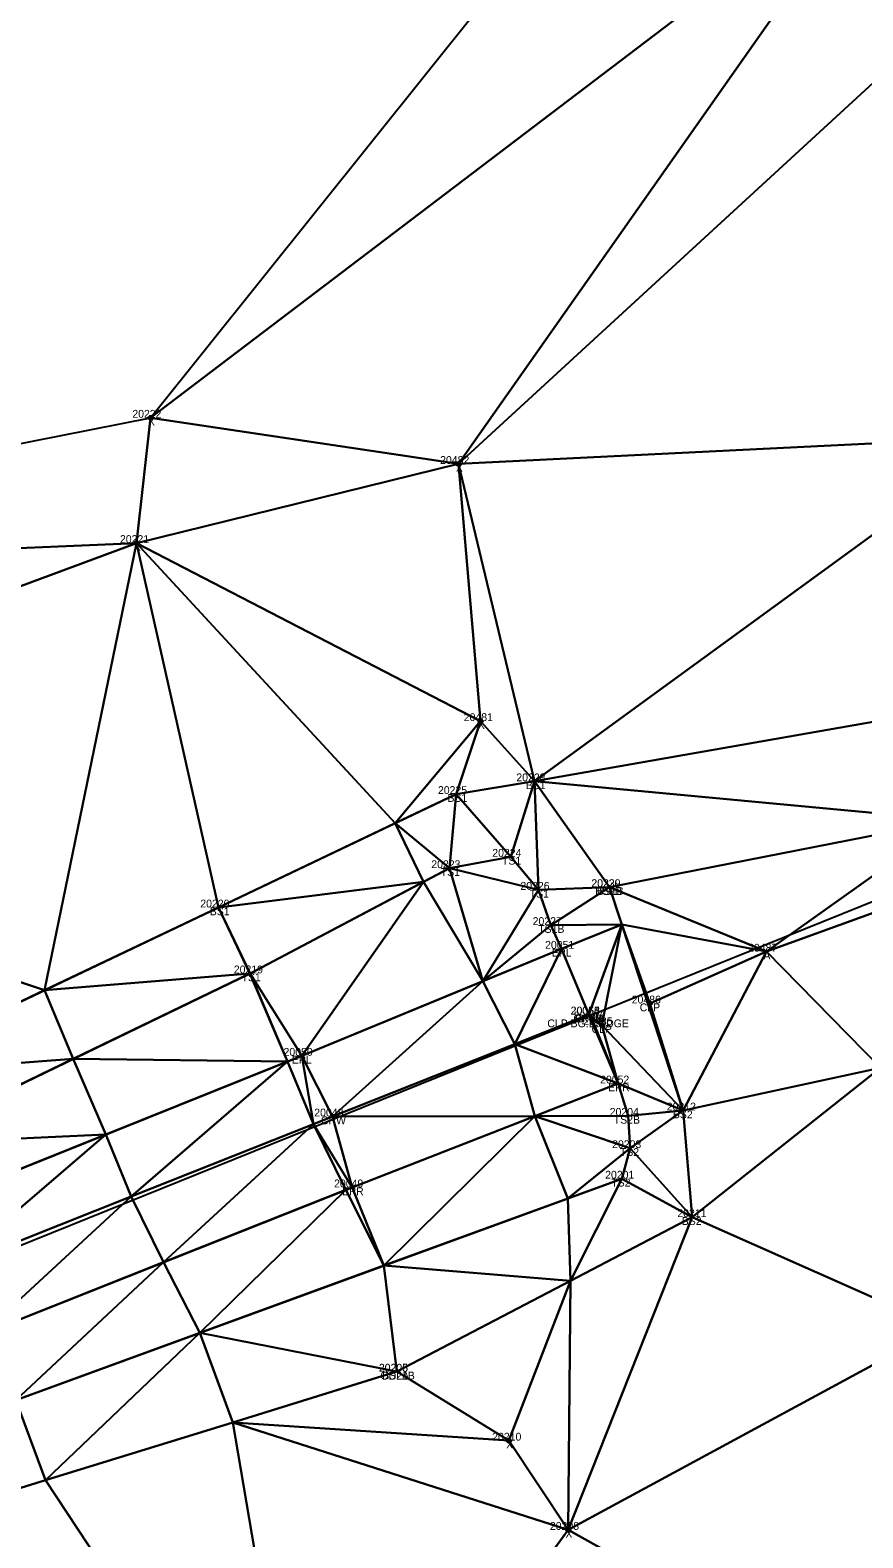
# Model space of a CAD drawing. Extents: x 1966740 to 1969291, y 1117379 to 1118460.
# Drawn here: x 1967626.6 to 1967732.8, y 1117756 to 1117948.4 of the extents above; entities that cross this region are included whole.
import ezdxf

# ---------------------------------------------------------------- set-up
doc = ezdxf.new("R2010")
doc.units = 0
for name, color, linetype in [('Level 1', 7, 'Continuous'), ('Level 3', 7, 'Continuous'), ('Level 30', 7, 'Continuous'), ('Level 35', 7, 'Continuous'), ('Level 50', 7, 'Continuous'), ('Level 52', 7, 'Continuous'), ('Level 53', 7, 'Continuous'), ('Level 56', 7, 'Continuous'), ('Level 6', 7, 'Continuous'), ('Level 62', 7, 'Continuous')]:
    doc.layers.add(name, color=color, linetype=linetype)

msp = doc.modelspace()

# ---------------------------------------------------------------- linework, layer by layer
at = {"layer": 'Level 1'}
msp.add_line((1966770.74, 1117448.12), (1967849.47, 1117883.86), dxfattribs=at)
at = {"layer": 'Level 3'}
for points in [[(1967560.73, 1117793.63), (1967650.63, 1117836.46), (1967680.95, 1117850.94), (1967690.95, 1117852.56), (1967700.5, 1117839.06)], [(1966768.15, 1117461.43), (1966869.41, 1117499.34), (1967070.52, 1117582.35), (1967171.25, 1117624.02), (1967269.74, 1117664.9), (1967320.21, 1117685.71), (1967369.37, 1117708.48), (1967468.51, 1117746.66), (1967564.6, 1117784.47), (1967654.68, 1117828.05), (1967680.1, 1117841.48), (1967687.91, 1117842.93), (1967691.45, 1117838.71), (1967693.03, 1117834.22)], [(1967673.4, 1117777.22), (1967711.06, 1117796.94), (1967709.93, 1117810.55), (1967700.5, 1117839.06)], [(1966769.51, 1117457.48), (1966870.16, 1117497.34), (1966971.19, 1117538.95), (1967071.09, 1117580.24), (1967172.6, 1117621.53), (1967270.79, 1117661.66), (1967321.12, 1117682.57), (1967371.52, 1117702.88), (1967470.26, 1117741.55), (1967566.67, 1117779.5), (1967661.25, 1117817.53), (1967694.4, 1117831.19), (1967697.89, 1117822.8)], [(1966772.57, 1117449.88), (1966874.49, 1117489.87), (1966974.64, 1117529.93), (1967075.06, 1117571.68), (1967175.91, 1117613.34), (1967274.11, 1117653.69), (1967325.25, 1117674.8), (1967374.73, 1117695.01), (1967473.9, 1117733.1), (1967569.8, 1117771.9), (1967665.19, 1117809.79), (1967697.89, 1117822.8)], [(1967340.03, 1117669.86), (1967379.26, 1117686.2), (1967476.09, 1117724.39), (1967573.92, 1117763.51), (1967667.7, 1117800.74), (1967701.64, 1117814), (1967697.89, 1117822.8)], [(1967334.06, 1117655.75), (1967334.81, 1117659.44), (1967379.1, 1117675.46), (1967480.83, 1117718.27), (1967577.81, 1117756.42), (1967702.07, 1117801.85), (1967703.17, 1117805.75), (1967702.89, 1117809.87)]]:
    msp.add_lwpolyline(points, dxfattribs=at)
at = {"layer": 'Level 30'}
for centre in [(1967641.96, 1117898.96), (1967681.25, 1117893.06), (1967640.16, 1117882.97), (1967684.04, 1117860.25), (1967705.67, 1117824.21), (1967698.29, 1117822.17), (1967699.54, 1117821.44), (1967687.66, 1117768.42), (1967695.23, 1117757.03)]:
    msp.add_circle(centre, 0.25, dxfattribs=at)
at = {"layer": 'Level 35'}
for points in [[(1967641.96, 1117898.96), (1967761.22, 1118047.98), (1967735.17, 1117969.82)], [(1967641.96, 1117898.96), (1967735.17, 1117969.82), (1967681.25, 1117893.06)], [(1967681.25, 1117893.06), (1967735.17, 1117969.82), (1967736.25, 1117943.61)], [(1967681.25, 1117893.06), (1967736.25, 1117943.61), (1967751.24, 1117896.51)], [(1967539.35, 1117878.65), (1967641.96, 1117898.96), (1967640.16, 1117882.97)], [(1967640.16, 1117882.97), (1967641.96, 1117898.96), (1967681.25, 1117893.06)], [(1967681.25, 1117893.06), (1967751.24, 1117896.51), (1967690.95, 1117852.56)], [(1967690.95, 1117852.56), (1967751.24, 1117896.51), (1967752.37, 1117863.36)], [(1967640.16, 1117882.97), (1967681.25, 1117893.06), (1967684.04, 1117860.25)], [(1967681.25, 1117893.06), (1967690.95, 1117852.56), (1967684.04, 1117860.25)], [(1967539.35, 1117878.65), (1967640.16, 1117882.97), (1967553.36, 1117850.76)], [(1967553.36, 1117850.76), (1967640.16, 1117882.97), (1967628.44, 1117825.89)], [(1967628.44, 1117825.89), (1967640.16, 1117882.97), (1967650.63, 1117836.46)], [(1967640.16, 1117882.97), (1967684.04, 1117860.25), (1967673.18, 1117847.23)], [(1967640.16, 1117882.97), (1967673.18, 1117847.23), (1967650.63, 1117836.46)], [(1967690.95, 1117852.56), (1967752.37, 1117863.36), (1967744.11, 1117847.6)], [(1967673.18, 1117847.23), (1967684.04, 1117860.25), (1967680.95, 1117850.94)], [(1967680.95, 1117850.94), (1967684.04, 1117860.25), (1967690.95, 1117852.56)], [(1967680.95, 1117850.94), (1967690.95, 1117852.56), (1967687.91, 1117842.93)], [(1967687.91, 1117842.93), (1967690.95, 1117852.56), (1967691.45, 1117838.71)], [(1967690.95, 1117852.56), (1967744.11, 1117847.6), (1967700.5, 1117839.06)], [(1967690.95, 1117852.56), (1967700.5, 1117839.06), (1967691.45, 1117838.71)], [(1967553.36, 1117850.76), (1967628.44, 1117825.89), (1967605.87, 1117815.14)], [(1967673.18, 1117847.23), (1967680.95, 1117850.94), (1967680.1, 1117841.48)], [(1967680.1, 1117841.48), (1967680.95, 1117850.94), (1967687.91, 1117842.93)], [(1967700.5, 1117839.06), (1967744.11, 1117847.6), (1967720.54, 1117830.82)], [(1967720.54, 1117830.82), (1967744.11, 1117847.6), (1967739.07, 1117837.57)], [(1967650.63, 1117836.46), (1967673.18, 1117847.23), (1967676.78, 1117839.73)], [(1967673.18, 1117847.23), (1967680.1, 1117841.48), (1967676.78, 1117839.73)], [(1967680.1, 1117841.48), (1967687.91, 1117842.93), (1967691.45, 1117838.71)], [(1967676.78, 1117839.73), (1967680.1, 1117841.48), (1967684.36, 1117827.05)], [(1967680.1, 1117841.48), (1967691.45, 1117838.71), (1967684.36, 1117827.05)], [(1967650.63, 1117836.46), (1967676.78, 1117839.73), (1967654.68, 1117828.05)], [(1967654.68, 1117828.05), (1967676.78, 1117839.73), (1967661.25, 1117817.53)], [(1967661.25, 1117817.53), (1967676.78, 1117839.73), (1967684.36, 1117827.05)], [(1967684.36, 1117827.05), (1967691.45, 1117838.71), (1967693.03, 1117834.22)], [(1967691.45, 1117838.71), (1967700.5, 1117839.06), (1967693.03, 1117834.22)], [(1967693.03, 1117834.22), (1967700.5, 1117839.06), (1967702.08, 1117834.28)], [(1967700.5, 1117839.06), (1967720.54, 1117830.82), (1967702.08, 1117834.28)], [(1967628.44, 1117825.89), (1967650.63, 1117836.46), (1967654.61, 1117828.02)], [(1967650.63, 1117836.46), (1967654.68, 1117828.05), (1967654.61, 1117828.02)], [(1967720.54, 1117830.82), (1967739.07, 1117837.57), (1967735.1, 1117816)], [(1967684.36, 1117827.05), (1967693.03, 1117834.22), (1967694.4, 1117831.19)], [(1967693.03, 1117834.22), (1967702.08, 1117834.28), (1967694.4, 1117831.19)], [(1967694.4, 1117831.19), (1967702.08, 1117834.28), (1967697.89, 1117822.8)], [(1967697.89, 1117822.8), (1967702.08, 1117834.28), (1967699.54, 1117821.44)], [(1967699.54, 1117821.44), (1967702.08, 1117834.28), (1967709.93, 1117810.55)], [(1967702.08, 1117834.28), (1967720.54, 1117830.82), (1967705.67, 1117824.21)], [(1967702.08, 1117834.28), (1967705.67, 1117824.21), (1967709.93, 1117810.55)], [(1967684.36, 1117827.05), (1967694.4, 1117831.19), (1967688.42, 1117819.03)], [(1967688.42, 1117819.03), (1967694.4, 1117831.19), (1967697.89, 1117822.8)], [(1967705.67, 1117824.21), (1967720.54, 1117830.82), (1967709.93, 1117810.55)], [(1967709.93, 1117810.55), (1967720.54, 1117830.82), (1967735.1, 1117816)], [(1967628.44, 1117825.89), (1967654.61, 1117828.02), (1967632.11, 1117817.13)], [(1967632.11, 1117817.13), (1967654.61, 1117828.02), (1967659.45, 1117816.8)], [(1967654.61, 1117828.02), (1967654.68, 1117828.05), (1967659.45, 1117816.8)], [(1967654.68, 1117828.05), (1967661.25, 1117817.53), (1967659.45, 1117816.8)], [(1967661.25, 1117817.53), (1967684.36, 1117827.05), (1967665.19, 1117809.79)], [(1967665.19, 1117809.79), (1967684.36, 1117827.05), (1967688.42, 1117819.03)], [(1967605.87, 1117815.14), (1967628.44, 1117825.89), (1967632.11, 1117817.13)], [(1967688.42, 1117819.03), (1967697.89, 1117822.8), (1967701.64, 1117814)], [(1967697.89, 1117822.8), (1967699.54, 1117821.44), (1967698.29, 1117822.17)], [(1967697.89, 1117822.8), (1967698.29, 1117822.17), (1967701.64, 1117814)], [(1967698.29, 1117822.17), (1967699.54, 1117821.44), (1967701.64, 1117814)], [(1967699.54, 1117821.44), (1967709.93, 1117810.55), (1967701.64, 1117814)], [(1967665.19, 1117809.79), (1967688.42, 1117819.03), (1967690.99, 1117809.84)], [(1967688.42, 1117819.03), (1967701.64, 1117814), (1967690.99, 1117809.84)], [(1967605.87, 1117815.14), (1967632.11, 1117817.13), (1967609.61, 1117806.25)], [(1967609.61, 1117806.25), (1967632.11, 1117817.13), (1967636.26, 1117807.48)], [(1967632.11, 1117817.13), (1967659.45, 1117816.8), (1967636.26, 1117807.48)], [(1967636.26, 1117807.48), (1967659.45, 1117816.8), (1967639.5, 1117799.59)], [(1967639.5, 1117799.59), (1967659.45, 1117816.8), (1967662.74, 1117808.82)], [(1967659.45, 1117816.8), (1967661.25, 1117817.53), (1967662.74, 1117808.82)], [(1967661.25, 1117817.53), (1967665.19, 1117809.79), (1967662.74, 1117808.82)], [(1967709.93, 1117810.55), (1967735.1, 1117816), (1967711.06, 1117796.94)], [(1967711.06, 1117796.94), (1967735.1, 1117816), (1967742.85, 1117782.8)], [(1967690.99, 1117809.84), (1967701.64, 1117814), (1967702.89, 1117809.87)], [(1967701.64, 1117814), (1967709.93, 1117810.55), (1967702.89, 1117809.87)], [(1967662.74, 1117808.82), (1967665.19, 1117809.79), (1967667.7, 1117800.74)], [(1967665.19, 1117809.79), (1967690.99, 1117809.84), (1967667.7, 1117800.74)], [(1967667.7, 1117800.74), (1967690.99, 1117809.84), (1967671.73, 1117790.76)], [(1967671.73, 1117790.76), (1967690.99, 1117809.84), (1967695.2, 1117799.34)], [(1967690.99, 1117809.84), (1967702.89, 1117809.87), (1967703.17, 1117805.75)], [(1967690.99, 1117809.84), (1967703.17, 1117805.75), (1967695.2, 1117799.34)], [(1967702.89, 1117809.87), (1967709.93, 1117810.55), (1967703.17, 1117805.75)], [(1967703.17, 1117805.75), (1967709.93, 1117810.55), (1967711.06, 1117796.94)], [(1967609.61, 1117806.25), (1967636.26, 1117807.48), (1967613.06, 1117798.15)], [(1967613.06, 1117798.15), (1967636.26, 1117807.48), (1967616.27, 1117790.36)], [(1967616.27, 1117790.36), (1967636.26, 1117807.48), (1967639.5, 1117799.59)], [(1967639.5, 1117799.59), (1967662.74, 1117808.82), (1967643.63, 1117791.18)], [(1967643.63, 1117791.18), (1967662.74, 1117808.82), (1967666.86, 1117800.41)], [(1967662.74, 1117808.82), (1967667.7, 1117800.74), (1967666.86, 1117800.41)], [(1967695.2, 1117799.34), (1967703.17, 1117805.75), (1967702.07, 1117801.85)], [(1967702.07, 1117801.85), (1967703.17, 1117805.75), (1967711.06, 1117796.94)], [(1967695.2, 1117799.34), (1967702.07, 1117801.85), (1967695.53, 1117788.81)], [(1967695.53, 1117788.81), (1967702.07, 1117801.85), (1967711.06, 1117796.94)], [(1967616.27, 1117790.36), (1967639.5, 1117799.59), (1967620.39, 1117781.96)], [(1967620.39, 1117781.96), (1967639.5, 1117799.59), (1967643.63, 1117791.18)], [(1967643.63, 1117791.18), (1967666.86, 1117800.41), (1967648.25, 1117782.17)], [(1967648.25, 1117782.17), (1967666.86, 1117800.41), (1967671.73, 1117790.76)], [(1967666.86, 1117800.41), (1967667.7, 1117800.74), (1967671.73, 1117790.76)], [(1967671.73, 1117790.76), (1967695.2, 1117799.34), (1967695.53, 1117788.81)], [(1967695.23, 1117757.03), (1967695.53, 1117788.81), (1967711.06, 1117796.94)], [(1967695.23, 1117757.03), (1967711.06, 1117796.94), (1967742.85, 1117782.8)], [(1967620.39, 1117781.96), (1967643.63, 1117791.18), (1967624.77, 1117773.59)], [(1967624.77, 1117773.59), (1967643.63, 1117791.18), (1967648.25, 1117782.17)], [(1967648.25, 1117782.17), (1967671.73, 1117790.76), (1967673.4, 1117777.22)], [(1967671.73, 1117790.76), (1967695.53, 1117788.81), (1967673.4, 1117777.22)], [(1967673.4, 1117777.22), (1967695.53, 1117788.81), (1967687.66, 1117768.42)], [(1967687.66, 1117768.42), (1967695.53, 1117788.81), (1967695.23, 1117757.03)], [(1967624.77, 1117773.59), (1967648.25, 1117782.17), (1967628.56, 1117763.37)], [(1967628.56, 1117763.37), (1967648.25, 1117782.17), (1967652.44, 1117770.75)], [(1967648.25, 1117782.17), (1967673.4, 1117777.22), (1967652.44, 1117770.75)], [(1967695.23, 1117757.03), (1967742.85, 1117782.8), (1967729.44, 1117737.88)], [(1967652.44, 1117770.75), (1967673.4, 1117777.22), (1967687.66, 1117768.42)], [(1967604.68, 1117755.99), (1967624.77, 1117773.59), (1967628.56, 1117763.37)], [(1967628.56, 1117763.37), (1967652.44, 1117770.75), (1967662.45, 1117711.98)], [(1967652.44, 1117770.75), (1967687.66, 1117768.42), (1967695.23, 1117757.03)], [(1967652.44, 1117770.75), (1967695.23, 1117757.03), (1967662.45, 1117711.98)], [(1967604.68, 1117755.99), (1967628.56, 1117763.37), (1967662.45, 1117711.98)], [(1967662.45, 1117711.98), (1967695.23, 1117757.03), (1967729.44, 1117737.88)]]:
    msp.add_lwpolyline(points, close=True, dxfattribs=at)
at = {"layer": 'Level 50'}
for centre in [(1967690.95, 1117852.56), (1967680.95, 1117850.94), (1967687.91, 1117842.93), (1967680.1, 1117841.48), (1967691.45, 1117838.71), (1967700.5, 1117839.06), (1967700.5, 1117839.06), (1967650.63, 1117836.46), (1967693.03, 1117834.22), (1967694.4, 1117831.19), (1967720.54, 1117830.82), (1967654.68, 1117828.05), (1967697.89, 1117822.8), (1967697.89, 1117822.8), (1967697.89, 1117822.8), (1967661.25, 1117817.53), (1967701.64, 1117814), (1967665.19, 1117809.79), (1967702.89, 1117809.87), (1967709.93, 1117810.55), (1967703.17, 1117805.75), (1967702.07, 1117801.85), (1967667.7, 1117800.74), (1967711.06, 1117796.94), (1967673.4, 1117777.22), (1967673.4, 1117777.22)]:
    msp.add_circle(centre, 0.001, dxfattribs=at)
at = {"layer": 'Level 6'}
for points in [[(1967720.54, 1117830.82), (1967739.07, 1117837.57), (1967744.11, 1117847.6), (1967769.01, 1117857.07), (1967779.54, 1117863.12), (1967775.75, 1117875.07), (1967791.02, 1117881), (1967800.46, 1117876.52)], [(1967336.04, 1117656.91), (1967380.56, 1117671.84), (1967483.89, 1117710.7), (1967580.8, 1117748.62), (1967673.4, 1117777.22)]]:
    msp.add_lwpolyline(points, dxfattribs=at)

# ---------------------------------------------------------------- texts
at = {"layer": 'Level 52'}
for s, p in [('20222', (1967639.64, 1117898.96)), ('20482', (1967678.91, 1117893.06)), ('20221', (1967638.06, 1117882.97)), ('20481', (1967681.92, 1117860.25)), ('20486', (1967703.35, 1117824.21)), ('20477', (1967695.94, 1117822.17)), ('20485', (1967697.19, 1117821.44)), ('20210', (1967685.55, 1117768.42)), ('20208', (1967692.91, 1117757.03))]:
    msp.add_text(s, height=1, dxfattribs=at).set_placement(p)
at = {"layer": 'Level 53'}
for s, p in [('20228', (1967688.63, 1117852.56)), ('20225', (1967678.63, 1117850.94)), ('BS1', (1967689.84, 1117851.56)), ('BS1', (1967679.84, 1117849.94)), ('20224', (1967685.56, 1117842.93)), ('20223', (1967677.78, 1117841.48)), ('TS1', (1967686.8, 1117841.93)), ('TS1', (1967678.99, 1117840.48)), ('20230', (1967698.19, 1117839.06)), ('20229', (1967698.21, 1117839.06)), ('20226', (1967689.15, 1117838.71)), ('TS1', (1967690.34, 1117837.71)), ('BS2B', (1967698.68, 1117838.06)), ('BS1B', (1967698.89, 1117838.06)), ('20220', (1967648.31, 1117836.46)), ('BS1', (1967649.52, 1117835.46)), ('20227', (1967690.71, 1117834.22)), ('TS1B', (1967691.42, 1117833.22)), ('20051', (1967692.3, 1117831.19)), ('EPL', (1967693.14, 1117830.19)), ('20219', (1967652.59, 1117828.05)), ('TS1', (1967653.57, 1117827.05)), ('20054', (1967695.55, 1117822.8)), ('20053', (1967695.57, 1117822.8)), ('20055', (1967695.57, 1117822.8)), ('CRWB', (1967695.9, 1117821.8)), ('EPRB', (1967696.09, 1117821.8)), ('EPLB', (1967696.14, 1117821.8)), ('20050', (1967658.93, 1117817.53)), ('EPL', (1967659.99, 1117816.53)), ('20052', (1967699.32, 1117814)), ('EPR', (1967700.33, 1117813)), ('20212', (1967707.82, 1117810.55)), ('20048', (1967662.85, 1117809.79)), ('CRW', (1967663.7, 1117808.79)), ('20204', (1967700.54, 1117809.87)), ('TS2B', (1967701.06, 1117808.87)), ('BS2', (1967708.6, 1117809.55)), ('20203', (1967700.85, 1117805.75)), ('TS2', (1967701.84, 1117804.75)), ('20049', (1967665.38, 1117800.74)), ('20201', (1967699.96, 1117801.85)), ('TS2', (1967700.74, 1117800.85)), ('EPR', (1967666.4, 1117799.74)), ('20211', (1967709.17, 1117796.94)), ('BS2', (1967709.73, 1117795.94)), ('20205', (1967671.08, 1117777.22)), ('20206', (1967671.1, 1117777.22)), ('ODL1B', (1967671.29, 1117776.22)), ('BS2A', (1967671.52, 1117776.22))]:
    msp.add_text(s, height=1, dxfattribs=at).set_placement(p)
at = {"layer": 'Level 56'}
for s, p in [('20487', (1967718.2, 1117830.82)), ('A', (1967720.16, 1117829.82))]:
    msp.add_text(s, height=1, dxfattribs=at).set_placement(p)
at = {"layer": 'Level 62'}
for s, p in [('X', (1967641.63, 1117897.96)), ('X', (1967680.92, 1117892.06)), ('X', (1967639.83, 1117881.97)), ('X', (1967683.71, 1117859.25)), ('CLP', (1967704.37, 1117823.21)), ('CLP BG.BRIDGE', (1967692.58, 1117821.17)), ('CLP', (1967698.23, 1117820.44)), ('X', (1967687.32, 1117767.42)), ('X', (1967694.89, 1117756.03))]:
    msp.add_text(s, height=1, dxfattribs=at).set_placement(p)

doc.saveas('drawing.dxf')
